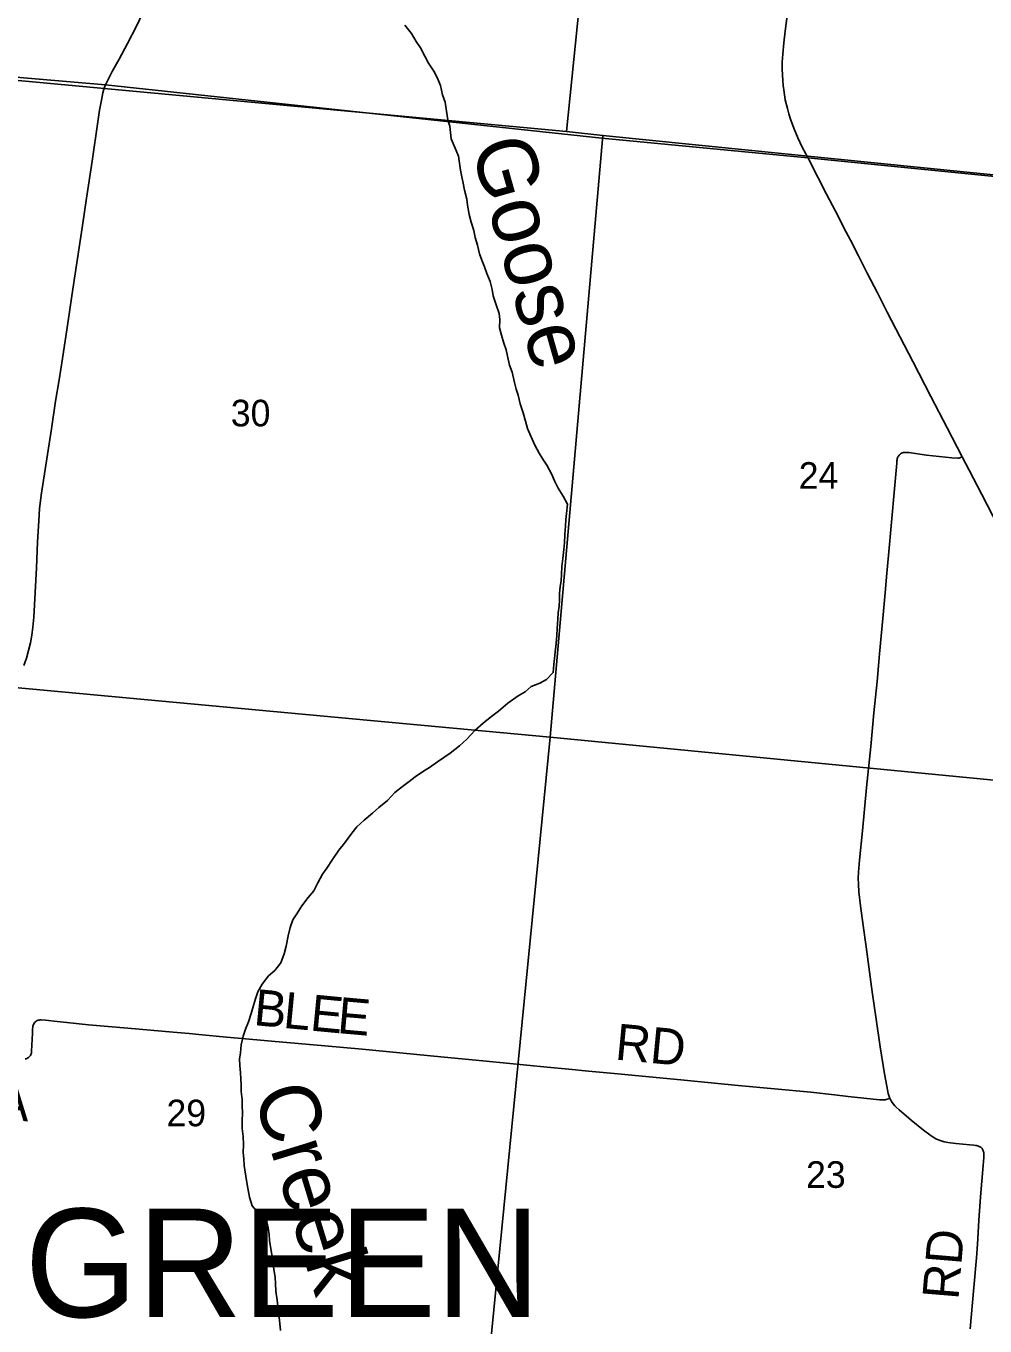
# Model space of a CAD drawing. Extents: x 1410790 to 1770854, y 566777 to 831614.
# Drawn here: x 1602980 to 1610939, y 671589 to 682381 of the extents above; entities that cross this region are included whole.
import ezdxf

# ---------------------------------------------------------------- set-up
doc = ezdxf.new("R2010")
doc.units = 0
for name, color, linetype in [('GM_X_County_Road', 7, 'Continuous'), ('GM_X_Minor_River', 7, 'Continuous'), ('GM_X_Minor_River_Text', 7, 'Continuous'), ('GM_X_Section', 7, 'Continuous'), ('GM_X_Section_Text', 7, 'Continuous'), ('GM_X_Township', 7, 'Continuous'), ('GM_X_Township_Road', 7, 'Continuous'), ('GM_X_Township_Road_Text', 7, 'Continuous'), ('GM_X_Township_Text', 7, 'Continuous')]:
    doc.layers.add(name, color=color, linetype=linetype)

msp = doc.modelspace()

# ---------------------------------------------------------------- linework, layer by layer
at = {"layer": 'GM_X_County_Road'}
for points in [[(1603627, 681855), (1603627, 681857), (1603627, 681857), (1603638, 681887), (1603640, 681891), (1603659, 681931), (1603696, 682004), (1603753, 682104), (1603823, 682234), (1603897, 682380), (1603947, 682484)], [(1609471, 681283), (1609469, 681286), (1609452, 681319), (1609422, 681375), (1609386, 681452), (1609352, 681532), (1609324, 681608), (1609312, 681651), (1609300, 681695), (1609282, 681769), (1609269, 681851), (1609265, 681887), (1609261, 681930), (1609258, 681972), (1609256, 682024), (1609256, 682081), (1609260, 682148), (1609269, 682240), (1609281, 682339), (1609298, 682464)], [(1602962, 677071), (1602983, 677133), (1603001, 677196), (1603016, 677260), (1603028, 677325), (1603037, 677390), (1603044, 677472), (1603066, 677882), (1603076, 678095), (1603086, 678275), (1603093, 678373), (1603107, 678487), (1603192, 679038), (1603226, 679265), (1603254, 679443), (1603282, 679621), (1603326, 679913), (1603360, 680140), (1603448, 680724), (1603483, 680951), (1603529, 681259), (1603576, 681584), (1603590, 681681), (1603608, 681778), (1603618, 681825), (1603627, 681855)], [(1610751, 678803), (1610625, 679045), (1610491, 679306), (1610339, 679597), (1610128, 680006), (1610046, 680165), (1609962, 680328), (1609888, 680472), (1609822, 680603), (1609769, 680705), (1609722, 680797), (1609625, 680985), (1609479, 681268), (1609471, 681283)], [(1611049, 678230), (1610913, 678492), (1610807, 678694), (1610751, 678803)]]:
    msp.add_lwpolyline(points, dxfattribs=at)
at = {"layer": 'GM_X_Minor_River'}
for points in [[(1606501, 676344), (1606578, 676405), (1606638, 676461), (1606705, 676532), (1606774, 676593), (1606832, 676641), (1606901, 676692), (1606979, 676760), (1607066, 676819), (1607122, 676854), (1607173, 676898), (1607245, 676925), (1607301, 676955), (1607356, 677014), (1607362, 677080), (1607367, 677130), (1607373, 677186), (1607380, 677256), (1607385, 677324), (1607389, 677380), (1607394, 677457), (1607398, 677509), (1607405, 677565), (1607407, 677615), (1607408, 677673), (1607413, 677725), (1607421, 677777), (1607425, 677827), (1607426, 677895), (1607435, 677961), (1607443, 678035), (1607448, 678089), (1607453, 678163), (1607457, 678229), (1607460, 678283), (1607466, 678335), (1607473, 678411), (1607438, 678478), (1607398, 678544), (1607367, 678605), (1607344, 678657), (1607304, 678734), (1607269, 678784), (1607239, 678834), (1607204, 678901), (1607169, 678975), (1607143, 679040), (1607126, 679100), (1607105, 679170), (1607081, 679245), (1607066, 679315), (1607048, 679367), (1607035, 679421), (1607014, 679508), (1606994, 679564), (1606975, 679640), (1606964, 679693), (1606946, 679749), (1606927, 679815), (1606909, 679875), (1606912, 679943), (1606907, 679994), (1606883, 680066), (1606858, 680142), (1606850, 680192), (1606831, 680261), (1606804, 680327), (1606784, 680381), (1606763, 680436), (1606743, 680490), (1606728, 680560), (1606709, 680625), (1606697, 680683), (1606676, 680753), (1606659, 680817), (1606645, 680894), (1606638, 680944), (1606618, 681018), (1606609, 681076), (1606596, 681129), (1606586, 681183), (1606579, 681241), (1606569, 681301), (1606542, 681367), (1606509, 681444), (1606498, 681548), (1606480, 681602), (1606469, 681675), (1606458, 681749), (1606438, 681809), (1606419, 681886), (1606399, 681938), (1606370, 681998), (1606321, 682071), (1606289, 682129), (1606254, 682198), (1606218, 682252), (1606179, 682319), (1606124, 682387)], [(1605093, 671552), (1605088, 671610), (1605082, 671660), (1605073, 671730), (1605065, 671803), (1605054, 671879), (1605051, 671941), (1605047, 671991), (1605038, 672061), (1605025, 672132), (1605021, 672182), (1605010, 672246), (1605002, 672298), (1604997, 672348), (1604991, 672404), (1604978, 672455), (1604916, 672519), (1604857, 672588), (1604834, 672659), (1604822, 672733), (1604809, 672797), (1604792, 672923), (1604787, 672978), (1604781, 673030), (1604786, 673096), (1604783, 673162), (1604775, 673230), (1604774, 673292), (1604777, 673360), (1604775, 673416), (1604774, 673469), (1604766, 673537), (1604767, 673589), (1604763, 673641), (1604760, 673691), (1604756, 673753), (1604751, 673805), (1604759, 673857), (1604766, 673923), (1604783, 673995), (1604803, 674053), (1604826, 674113), (1604849, 674183), (1604869, 674251), (1604886, 674305), (1604904, 674363), (1604941, 674428), (1604992, 674496), (1605044, 674540), (1605095, 674603), (1605123, 674679), (1605138, 674743), (1605157, 674829), (1605173, 674897), (1605194, 674961), (1605227, 675012), (1605269, 675078), (1605322, 675146), (1605368, 675203), (1605403, 675267), (1605440, 675339), (1605476, 675391), (1605525, 675462), (1605576, 675538), (1605624, 675597), (1605683, 675679), (1605725, 675733), (1605788, 675788), (1605856, 675845), (1605909, 675893), (1605980, 675952), (1606042, 676018), (1606105, 676069), (1606159, 676109), (1606211, 676148), (1606278, 676196), (1606328, 676225), (1606395, 676273), (1606447, 676308), (1606501, 676344)]]:
    msp.add_lwpolyline(points, dxfattribs=at)
at = {"layer": 'GM_X_Section'}
for points in [[(1607998, 686724), (1607465, 681505), (1602379, 681977), (1602165, 681998), (1602695, 687247)], [(1613594, 686127), (1612710, 680974), (1607768, 681473), (1607465, 681505), (1607998, 686724)], [(1602379, 681977), (1607465, 681505), (1607768, 681473), (1607330, 676476), (1601930, 676978)], [(1607768, 681473), (1612710, 680974), (1613061, 680930), (1612583, 675968), (1607330, 676476)], [(1607330, 676476), (1606796, 671049), (1601438, 671529), (1601930, 676978)], [(1607330, 676476), (1612583, 675968), (1612039, 670539), (1606796, 671049)]]:
    msp.add_lwpolyline(points, close=True, dxfattribs=at)
at = {"layer": 'GM_X_Township'}
for points in [[(1629570, 687086), (1628688, 679300), (1628420, 679330), (1628062, 679372), (1627883, 679391), (1627721, 679408), (1626002, 679596), (1623846, 679835), (1620640, 680162), (1618425, 680390), (1615342, 680699), (1609469, 681286), (1607758, 681450), (1603640, 681891), (1599590, 682237), (1597079, 682470)], [(1626163, 656988), (1626861, 663024), (1627499, 668268), (1627873, 671881), (1628103, 674059), (1628688, 679300), (1628420, 679330), (1628062, 679372), (1627883, 679391), (1627721, 679408), (1626002, 679596), (1623846, 679835), (1620640, 680162), (1618425, 680390), (1615342, 680699), (1609469, 681286), (1607758, 681450), (1603640, 681891), (1599590, 682237)]]:
    msp.add_lwpolyline(points, dxfattribs=at)
at = {"layer": 'GM_X_Township_Road'}
for points in [[(1610149, 673479), (1610140, 673504), (1610135, 673520), (1610132, 673536), (1610106, 673682), (1610070, 673908), (1610035, 674135), (1610003, 674363), (1609952, 674737), (1609929, 674915), (1609907, 675078), (1609893, 675192), (1609888, 675258), (1609887, 675307), (1609889, 675357), (1609897, 675455), (1609923, 675700), (1609957, 676059), (1609992, 676401), (1610016, 676679), (1610043, 676940), (1610064, 677168), (1610092, 677462), (1610111, 677675), (1610125, 677838), (1610138, 677985), (1610189, 678540), (1610205, 678720), (1610207, 678752), (1610208, 678770), (1610209, 678778), (1610211, 678787), (1610213, 678795), (1610217, 678803), (1610221, 678811), (1610227, 678819), (1610233, 678824), (1610239, 678830), (1610246, 678834), (1610254, 678837), (1610263, 678839), (1610272, 678840), (1610290, 678840), (1610306, 678839), (1610453, 678819), (1610665, 678796), (1610714, 678792), (1610723, 678793), (1610730, 678795), (1610751, 678803)], [(1602972, 673806), (1602981, 673807), (1602988, 673810), (1602995, 673814), (1603001, 673818), (1603007, 673823), (1603012, 673828), (1603016, 673835), (1603020, 673842), (1603022, 673848), (1603025, 673855), (1603026, 673862), (1603027, 673872), (1603034, 674019), (1603035, 674052), (1603037, 674069), (1603038, 674078), (1603040, 674086), (1603042, 674093), (1603047, 674101), (1603051, 674108), (1603058, 674115), (1603064, 674119), (1603073, 674124), (1603081, 674127), (1603089, 674129), (1603097, 674130), (1603106, 674131), (1603141, 674128), (1603238, 674116), (1603319, 674108), (1603499, 674090), (1603826, 674062), (1604202, 674028), (1604333, 674017), (1604414, 674008), (1604643, 673988), (1604741, 673980), (1605018, 673955), (1605460, 673915), (1605770, 673888), (1606423, 673824), (1606799, 673789), (1607305, 673739), (1607485, 673721), (1607648, 673705), (1607861, 673685), (1608416, 673632), (1608694, 673606), (1608890, 673587), (1609494, 673529), (1609690, 673509), (1609804, 673495), (1609935, 673481), (1610065, 673468), (1610097, 673466), (1610105, 673467), (1610112, 673468), (1610127, 673472), (1610149, 673479)], [(1610816, 671566), (1610847, 671909), (1610868, 672154), (1610877, 672268), (1610889, 672464), (1610903, 672661), (1610923, 672922), (1610929, 672988), (1610930, 673004), (1610929, 673020), (1610929, 673029), (1610927, 673036), (1610925, 673043), (1610922, 673050), (1610918, 673057), (1610915, 673062), (1610910, 673068), (1610904, 673073), (1610897, 673077), (1610891, 673080), (1610884, 673083), (1610877, 673085), (1610869, 673087), (1610861, 673089), (1610847, 673091), (1610812, 673093), (1610698, 673104), (1610632, 673112), (1610617, 673115), (1610600, 673119), (1610583, 673123), (1610568, 673128), (1610554, 673134), (1610537, 673141), (1610523, 673149), (1610508, 673158), (1610481, 673176), (1610428, 673216), (1610327, 673299), (1610226, 673383), (1610202, 673406), (1610190, 673418), (1610179, 673430), (1610169, 673444), (1610160, 673458), (1610154, 673469), (1610149, 673479)]]:
    msp.add_lwpolyline(points, dxfattribs=at)

# ---------------------------------------------------------------- texts
at = {"layer": 'GM_X_Minor_River_Text'}
for s, rotation, p in [('Goose', 285.8001, (1606669, 681389)), ('Creek', 287.0165, (1604864, 673524))]:
    msp.add_text(s, height=499.9, rotation=rotation, dxfattribs=at).set_placement(p)
at = {"layer": 'GM_X_Section_Text'}
for s, p in [('30', (1604680, 679057)), ('24', (1609393, 678539)), ('29', (1604146, 673247)), ('23', (1609454, 672736))]:
    msp.add_text(s, height=221, rotation=0, dxfattribs=at).set_placement(p)
at = {"layer": 'GM_X_Township_Road_Text'}
for s, rotation, p in [('B', 354.5333, (1604863, 674088)), ('L', 354.5342, (1605108, 674065)), ('E', 354.5389, (1605331, 674043)), ('E', 354.8824, (1605557, 674022)), ('RD', 354.5364, (1607863, 673802)), ('A', 356.8174, (1602730, 673303)), ('RD', 85.1969, (1610718, 671802))]:
    msp.add_text(s, height=300, rotation=rotation, dxfattribs=at).set_placement(p)
at = {"layer": 'GM_X_Township_Text'}
msp.add_text('GREEN', height=900, rotation=0, dxfattribs=at).set_placement((1602970, 671663))

doc.saveas('drawing.dxf')
